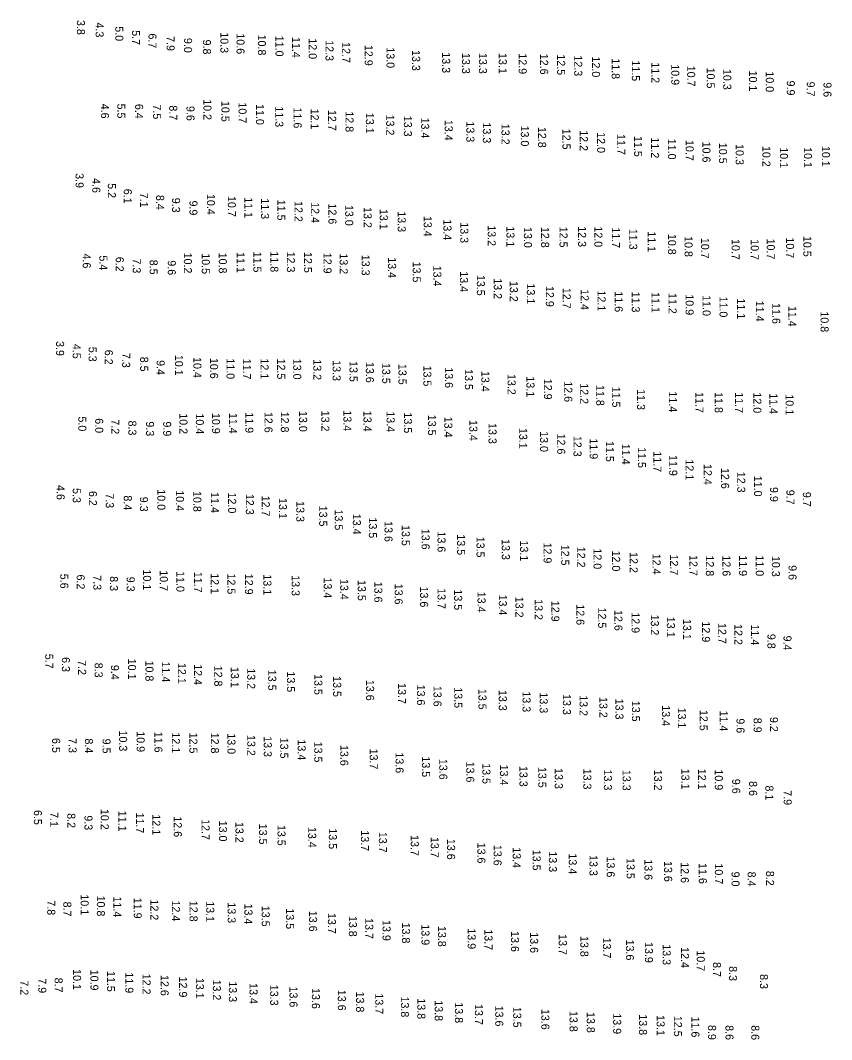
# Model space of a CAD drawing. Extents: x 988130 to 1132882, y 654656 to 841453.
# Drawn here: x 1112035 to 1112542, y 658070 to 658706 of the extents above; entities that cross this region are included whole.
import ezdxf

# ---------------------------------------------------------------- set-up
doc = ezdxf.new("R2010")
doc.units = 0
doc.layers.add('V-TOPO-SOUN', color=7, linetype='Continuous')

msp = doc.modelspace()

# ---------------------------------------------------------------- texts
at = {"layer": 'V-TOPO-SOUN'}
for s, p in [('3.8', (1112070.72, 658706.48)), ('4.3', (1112082.4, 658704.91)), ('5.0', (1112094.72, 658702.53)), ('5.7', (1112105.12, 658700.11)), ('6.7', (1112115.4, 658698.07)), ('7.9', (1112126.73, 658696.4)), ('9.0', (1112137.63, 658695.27)), ('10.3 ', (1112160.31, 658698.8)), ('10.6 ', (1112170.38, 658698.14)), ('10.8 ', (1112183.74, 658697.36)), ('11.0 ', (1112194.7, 658696.66)), ('11.4 ', (1112205.07, 658695.88)), ('9.8', (1112149.4, 658694.23)), ('12.0 ', (1112215.47, 658695.04)), ('12.3 ', (1112225.94, 658693.86)), ('12.7 ', (1112236.35, 658692.64)), ('12.9 ', (1112250.38, 658690.9)), ('13.0 ', (1112264.01, 658689.42)), ('13.3 ', (1112280.01, 658687.68)), ('13.3 ', (1112298.74, 658686.31)), ('13.3 ', (1112311.15, 658685.88)), ('13.3 ', (1112321.71, 658685.88)), ('13.1 ', (1112334.11, 658685.84)), ('12.9 ', (1112346.54, 658685.65)), ('12.6 ', (1112359.92, 658685.38)), ('12.5 ', (1112370.54, 658685)), ('12.3 ', (1112381.22, 658684.35)), ('12.0 ', (1112392.28, 658683.68)), ('11.8 ', (1112404.59, 658682.55)), ('11.5 ', (1112417.19, 658681.25)), ('11.2 ', (1112429.41, 658680.02)), ('10.9 ', (1112441.78, 658678.81)), ('10.7 ', (1112451.74, 658677.91)), ('10.5 ', (1112463.94, 658676.73)), ('10.3 ', (1112474.25, 658675.87)), ('10.1 ', (1112490.34, 658674.87)), ('10.0 ', (1112500.78, 658674.37)), ('9.9', (1112513.94, 658668.62)), ('9.7', (1112526.38, 658667.98)), ('9.6', (1112536.81, 658667.57)), ('10.2 ', (1112149.73, 658656.98)), ('4.6', (1112085.75, 658654.18)), ('5.5', (1112095.95, 658654.26)), ('6.4', (1112107.07, 658654.05)), ('7.5', (1112118.26, 658653.72)), ('8.7', (1112128.35, 658653.14)), ('9.6', (1112139.15, 658652.75)), ('10.5 ', (1112160.96, 658655.89)), ('10.7 ', (1112171.65, 658654.99)), ('11.0 ', (1112182.53, 658653.93)), ('11.3 ', (1112194.57, 658652.56)), ('11.6 ', (1112206, 658651.8)), ('12.1 ', (1112216.73, 658651.12)), ('12.7 ', (1112227.58, 658650.29)), ('12.8 ', (1112238.42, 658649.41)), ('13.1 ', (1112251.15, 658648.49)), ('13.2 ', (1112263.83, 658647.36)), ('13.3 ', (1112274.86, 658646.63)), ('13.4 ', (1112285.65, 658645.53)), ('13.4 ', (1112300.34, 658644.11)), ('13.3 ', (1112313.88, 658643.13)), ('13.3 ', (1112324.17, 658642.46)), ('13.2 ', (1112335.81, 658641.64)), ('13.0 ', (1112347.88, 658640.53)), ('12.8 ', (1112358.67, 658639.68)), ('12.5 ', (1112373.88, 658638.55)), ('12.2 ', (1112384.7, 658637.6)), ('12.0 ', (1112395.49, 658636.38)), ('11.7 ', (1112408.02, 658635.25)), ('11.5 ', (1112418.6, 658634.02)), ('11.2 ', (1112429.18, 658633.08)), ('11.0 ', (1112439.72, 658632.28)), ('10.7 ', (1112450.78, 658631.49)), ('10.6 ', (1112461.25, 658630.48)), ('10.5 ', (1112471.61, 658629.75)), ('10.3 ', (1112482.01, 658628.96)), ('10.2 ', (1112498.67, 658627.8)), ('10.1 ', (1112509.63, 658626.96)), ('10.1 ', (1112524.61, 658627.05)), ('10.1 ', (1112535.82, 658627.81)), ('3.9', (1112069.9, 658610.79)), ('4.6', (1112080.33, 658607.7)), ('5.2', (1112090.03, 658604.5)), ('6.1', (1112099.98, 658601.01)), ('7.1', (1112110.15, 658598.58)), ('8.4', (1112120.19, 658597.17)), ('9.3', (1112130.13, 658595.4)), ('9.9', (1112140.98, 658593.69)), ('10.4 ', (1112151.9, 658597.78)), ('10.7 ', (1112164.96, 658596.51)), ('11.1 ', (1112175.34, 658595.76)), ('11.3 ', (1112185.66, 658595.09)), ('11.5 ', (1112195.85, 658594.22)), ('12.2 ', (1112206.6, 658593.38)), ('12.4 ', (1112217, 658592.66)), ('12.6 ', (1112227.76, 658591.85)), ('13.0 ', (1112238.23, 658590.95)), ('13.2 ', (1112249.77, 658589.63)), ('13.1 ', (1112259.78, 658588.47)), ('13.3 ', (1112271, 658586.99)), ('13.4 ', (1112287.24, 658584.09)), ('13.4 ', (1112299.57, 658581.92)), ('13.3 ', (1112310.09, 658580.13)), ('13.2 ', (1112327.17, 658578.25)), ('13.1 ', (1112338.88, 658577.56)), ('13.0 ', (1112349.79, 658577.14)), ('12.8 ', (1112360.54, 658577.2)), ('12.5 ', (1112372.03, 658577.35)), ('12.3 ', (1112383.64, 658577.63)), ('12.0 ', (1112393.77, 658577.54)), ('11.7 ', (1112404.7, 658576.99)), ('11.3 ', (1112415.57, 658576.02)), ('11.1 ', (1112427.08, 658574.49)), ('10.8 ', (1112439.8, 658572.86)), ('10.8 ', (1112450.1, 658571.47)), ('10.7 ', (1112460.44, 658570.37)), ('10.7 ', (1112479.5, 658569.62)), ('10.7 ', (1112491.42, 658569.54)), ('10.7 ', (1112501.43, 658569.94)), ('10.7 ', (1112513.46, 658570.63)), ('10.5 ', (1112524.25, 658571.58)), ('11.1 ', (1112170.46, 658561.48)), ('11.5 ', (1112180.89, 658561.78)), ('11.8 ', (1112191.52, 658561.92)), ('12.3 ', (1112201.82, 658561.8)), ('12.5 ', (1112212.51, 658561.55)), ('4.6', (1112074.36, 658560.58)), ('5.4', (1112084.75, 658559.42)), ('6.2', (1112094.97, 658558.54)), ('7.3', (1112105.58, 658557.51)), ('8.5', (1112116.16, 658556.71)), ('9.6', (1112127.46, 658556.33)), ('10.2 ', (1112137.5, 658561.15)), ('10.5 ', (1112148.69, 658560.76)), ('10.8 ', (1112159.31, 658561.13)), ('12.9 ', (1112224.7, 658561.08)), ('13.2 ', (1112234.78, 658560.69)), ('13.3 ', (1112248.51, 658559.82)), ('13.4 ', (1112264.99, 658558.28)), ('13.5 ', (1112280.38, 658555.55)), ('13.4 ', (1112293.21, 658553.03)), ('13.4 ', (1112309.87, 658549.49)), ('13.5 ', (1112320.42, 658547.24)), ('13.2 ', (1112331.01, 658545.14)), ('13.2 ', (1112341, 658543.47)), ('13.1 ', (1112351.63, 658541.88)), ('12.9 ', (1112363.48, 658540.29)), ('12.7 ', (1112374.03, 658539.16)), ('12.4 ', (1112385.25, 658538.31)), ('12.1 ', (1112395.79, 658537.5)), ('11.6 ', (1112406.47, 658536.97)), ('11.3 ', (1112417.12, 658536.81)), ('11.1 ', (1112429.52, 658536.47)), ('11.2 ', (1112440.13, 658535.92)), ('10.9 ', (1112450.75, 658535.09)), ('11.0 ', (1112461.35, 658534.56)), ('11.0 ', (1112471.9, 658533.72)), ('11.1 ', (1112482.91, 658532.56)), ('11.4 ', (1112494.6, 658531.07)), ('11.6 ', (1112504.85, 658529.6)), ('11.4 ', (1112514.92, 658527.87)), ('10.8 ', (1112535.02, 658524.44)), ('3.9', (1112057.73, 658505.88)), ('4.5', (1112068.1, 658504.15)), ('5.3', (1112078.07, 658502.32)), ('6.2', (1112088.14, 658500.46)), ('7.3', (1112099, 658498.5)), ('8.5', (1112110.22, 658496.11)), ('9.4', (1112120.52, 658493.99)), ('10.1 ', (1112131.97, 658497.29)), ('10.4 ', (1112143.44, 658495.9)), ('10.6 ', (1112153.87, 658495.39)), ('11.0 ', (1112164.13, 658495.12)), ('11.7 ', (1112174.37, 658494.93)), ('12.1 ', (1112185.38, 658495.06)), ('12.5 ', (1112195.74, 658494.97)), ('13.0 ', (1112205.78, 658494.85)), ('13.2 ', (1112218.31, 658494.51)), ('13.3 ', (1112230.38, 658493.96)), ('13.5 ', (1112240.92, 658493.41)), ('13.6 ', (1112251.11, 658492.86)), ('13.5 ', (1112261.32, 658492.24)), ('13.5 ', (1112271.49, 658491.66)), ('13.5 ', (1112287.02, 658490.61)), ('13.6 ', (1112300.49, 658489.53)), ('13.5 ', (1112312.95, 658488.37)), ('13.4 ', (1112323.22, 658487.25)), ('13.2 ', (1112339.62, 658485.35)), ('13.1 ', (1112351.39, 658483.86)), ('12.9 ', (1112362.3, 658482.36)), ('12.6 ', (1112374.98, 658480.78)), ('12.2 ', (1112384.98, 658479.57)), ('11.8 ', (1112394.95, 658478.45)), ('11.5 ', (1112404.93, 658477.44)), ('11.3 ', (1112420.42, 658475.86)), ('11.4 ', (1112440.33, 658474.45)), ('11.7 ', (1112456.87, 658474.06)), ('11.8 ', (1112468.96, 658473.99)), ('11.7 ', (1112481.66, 658473.94)), ('12.0 ', (1112493.04, 658473.82)), ('11.4 ', (1112503.11, 658473.32)), ('10.1 ', (1112513.17, 658472.61)), ('10.2 ', (1112134.75, 658460.8)), ('10.4 ', (1112144.97, 658460.7)), ('10.9 ', (1112155.04, 658460.97)), ('11.4 ', (1112165.75, 658461.04)), ('11.9 ', (1112175.87, 658461.42)), ('12.6 ', (1112187.85, 658461.66)), ('12.8 ', (1112198.04, 658461.8)), ('13.0 ', (1112209.46, 658462.24)), ('13.2 ', (1112223.3, 658462.42)), ('13.4 ', (1112237.11, 658462.62)), ('13.4 ', (1112249.64, 658462.34)), ('13.4 ', (1112264.08, 658462.03)), ('13.5 ', (1112274.91, 658461.29)), ('13.5 ', (1112289.96, 658459.88)), ('5.0', (1112071.61, 658458.81)), ('6.0', (1112082.14, 658457.68)), ('7.2', (1112092.21, 658457)), ('8.3', (1112102.87, 658456.24)), ('9.3', (1112113.9, 658455.73)), ('9.9', (1112124.59, 658455.69)), ('13.4 ', (1112300.11, 658458.65)), ('13.4 ', (1112315.74, 658456.58)), ('13.3 ', (1112327.71, 658454.67)), ('13.1 ', (1112346.83, 658451.64)), ('13.0 ', (1112359.88, 658449.62)), ('12.6 ', (1112370.6, 658448.12)), ('12.3 ', (1112380.77, 658446.69)), ('11.9 ', (1112390.88, 658445.1)), ('11.5 ', (1112400.96, 658443.43)), ('11.4 ', (1112410.98, 658441.74)), ('11.5 ', (1112420.96, 658439.63)), ('11.7 ', (1112430.67, 658437.03)), ('11.9 ', (1112440.53, 658434.69)), ('12.1 ', (1112450.74, 658431.99)), ('12.4 ', (1112462.08, 658429.1)), ('12.6 ', (1112472.93, 658426.63)), ('12.3 ', (1112482.97, 658424.24)), ('11.0 ', (1112493.44, 658421.75)), ('4.6', (1112058.09, 658415.96)), ('5.3', (1112068.13, 658414.07)), ('6.2', (1112078.23, 658412.27)), ('7.3', (1112088.76, 658410.8)), ('8.4', (1112100.01, 658409.51)), ('9.3', (1112110.08, 658408.65)), ('10.0 ', (1112120.91, 658413.28)), ('10.4 ', (1112132.53, 658412.67)), ('10.8 ', (1112143.37, 658412.22)), ('11.4 ', (1112154.39, 658411.54)), ('12.0 ', (1112165.12, 658411.28)), ('12.3 ', (1112176.2, 658410.43)), ('12.7 ', (1112186.16, 658409.36)), ('9.9', (1112503.47, 658414.72)), ('9.7', (1112513.7, 658413)), ('9.7', (1112523.96, 658411.69)), ('13.1 ', (1112196.82, 658407.85)), ('13.3 ', (1112207.7, 658405.92)), ('13.5 ', (1112221.97, 658403.06)), ('13.5 ', (1112231.73, 658400.69)), ('13.4 ', (1112243, 658397.99)), ('13.5 ', (1112253.01, 658395.72)), ('13.6 ', (1112262.77, 658393.42)), ('13.5 ', (1112273.53, 658390.99)), ('13.6 ', (1112285.93, 658388.64)), ('13.6 ', (1112295.86, 658386.95)), ('13.5 ', (1112308.09, 658385.17)), ('13.5 ', (1112320.2, 658383.69)), ('13.3 ', (1112336, 658382.19)), ('13.1 ', (1112347.44, 658381.32)), ('12.9 ', (1112362.08, 658380.03)), ('12.5 ', (1112373.09, 658378.69)), ('12.2 ', (1112383.07, 658377.44)), ('12.0 ', (1112393.25, 658376.37)), ('12.0 ', (1112404.88, 658375.03)), ('12.2 ', (1112415.85, 658374.05)), ('12.4 ', (1112430.11, 658373.08)), ('12.7 ', (1112441.04, 658372.57)), ('12.7 ', (1112453.16, 658372.24)), ('12.8 ', (1112463.39, 658371.99)), ('12.6 ', (1112473.77, 658371.99)), ('11.9 ', (1112484.08, 658372.09)), ('11.0 ', (1112494.52, 658372.01)), ('10.3 ', (1112504.61, 658371.67)), ('9.6', (1112515.03, 658365.91)), ('5.6', (1112060.35, 658360.55)), ('6.2', (1112070.6, 658360.05)), ('7.3', (1112080.97, 658359.62)), ('8.3', (1112091.32, 658359)), ('9.3', (1112101.79, 658358.67)), ('10.1 ', (1112112.04, 658363.23)), ('10.7 ', (1112122.48, 658362.72)), ('11.0 ', (1112132.8, 658362.16)), ('11.7 ', (1112143.89, 658361.75)), ('12.1 ', (1112154.29, 658360.88)), ('12.5 ', (1112164.69, 658360.7)), ('12.9 ', (1112175.65, 658360.53)), ('13.1 ', (1112187.15, 658360.18)), ('13.3 ', (1112204.78, 658359.66)), ('13.4 ', (1112224.84, 658358.19)), ('13.4 ', (1112235.1, 658357.29)), ('13.5 ', (1112246.09, 658356.66)), ('13.6 ', (1112256.4, 658355.59)), ('13.6 ', (1112269.13, 658354.34)), ('13.6 ', (1112284.98, 658352.57)), ('13.7 ', (1112295.88, 658351.54)), ('13.5 ', (1112306.24, 658350.76)), ('13.4 ', (1112320.84, 658349.35)), ('13.4 ', (1112334.16, 658347.55)), ('13.2 ', (1112344.49, 658346.18)), ('13.2 ', (1112356.49, 658344.67)), ('12.9 ', (1112366.93, 658343.64)), ('12.6 ', (1112382.54, 658341.47)), ('12.5 ', (1112396.15, 658339.44)), ('12.6 ', (1112406.3, 658337.89)), ('12.9 ', (1112417, 658336.48)), ('13.2 ', (1112429.04, 658335.06)), ('13.1 ', (1112439.06, 658333.67)), ('13.1 ', (1112449.2, 658332.31)), ('12.9 ', (1112461.01, 658330.74)), ('12.7 ', (1112471.13, 658329.77)), ('12.2 ', (1112481.2, 658329.08)), ('11.4 ', (1112491.61, 658328.83)), ('9.8', (1112501.85, 658322.99)), ('9.4', (1112511.85, 658321.92)), ('5.7', (1112050.96, 658310.56)), ('6.3', (1112061.35, 658308.47)), ('7.2', (1112071.49, 658306.55)), ('10.1 ', (1112102.65, 658307.5)), ('8.3', (1112081.82, 658304.98)), ('9.4', (1112091.98, 658303.6)), ('10.8 ', (1112113.53, 658306.32)), ('11.4 ', (1112123.75, 658305.71)), ('12.1 ', (1112133.8, 658304.82)), ('12.4 ', (1112143.82, 658304.03)), ('12.8 ', (1112156.47, 658303.13)), ('13.1 ', (1112166.81, 658302.33)), ('13.2 ', (1112177.04, 658301.53)), ('13.5 ', (1112190.17, 658300.55)), ('13.5 ', (1112201.87, 658299.52)), ('13.5 ', (1112218.94, 658297.88)), ('13.5 ', (1112230.7, 658296.58)), ('13.6 ', (1112251.29, 658294.26)), ('13.7 ', (1112271.17, 658292.23)), ('13.6 ', (1112283.01, 658291.28)), ('13.6 ', (1112293.35, 658290.53)), ('13.5 ', (1112306.32, 658289.62)), ('13.5 ', (1112321.43, 658288.66)), ('13.3 ', (1112334.1, 658287.98)), ('13.3 ', (1112348.95, 658287.06)), ('13.3 ', (1112359.66, 658286.41)), ('13.3 ', (1112374.12, 658285.38)), ('13.2 ', (1112384.54, 658284.67)), ('13.2 ', (1112396.92, 658283.56)), ('13.3 ', (1112406.94, 658282.5)), ('13.5 ', (1112417.24, 658281.18)), ('13.4 ', (1112436.01, 658278.37)), ('13.1 ', (1112445.95, 658276.93)), ('12.5 ', (1112459.5, 658275.48)), ('11.4 ', (1112472.09, 658275.08)), ('9.6', (1112482.52, 658270.2)), ('8.9', (1112493.21, 658270.57)), ('9.2', (1112503.43, 658271.07)), ('10.3 ', (1112097.1, 658262.62)), ('10.9 ', (1112108.03, 658262.14)), ('6.5', (1112055.25, 658257.95)), ('7.3', (1112065.56, 658257.9)), ('8.4', (1112075.75, 658257.65)), ('9.5', (1112086.75, 658257.54)), ('11.6 ', (1112119.12, 658261.86)), ('12.1 ', (1112130.05, 658261.46)), ('12.5 ', (1112140.95, 658261.3)), ('12.8 ', (1112154.38, 658261.28)), ('13.0 ', (1112164.71, 658260.85)), ('13.2 ', (1112177.09, 658259.8)), ('13.3 ', (1112187.38, 658259.08)), ('13.5 ', (1112197.66, 658258.15)), ('13.4 ', (1112208.58, 658257.03)), ('13.5 ', (1112218.91, 658255.67)), ('13.6 ', (1112235.16, 658253.6)), ('13.7 ', (1112253.55, 658251.34)), ('13.6 ', (1112269.68, 658248.96)), ('13.5 ', (1112286.19, 658246.45)), ('13.6 ', (1112296.94, 658244.91)), ('13.6 ', (1112313.81, 658243.21)), ('13.5 ', (1112323.88, 658242.21)), ('13.4 ', (1112334.9, 658241.32)), ('13.3 ', (1112347.03, 658240.5)), ('13.5 ', (1112358.77, 658239.89)), ('13.3 ', (1112369.08, 658239.12)), ('13.3 ', (1112386.87, 658238.8)), ('13.3 ', (1112399.74, 658238.24)), ('13.3 ', (1112411.42, 658238.04)), ('13.2 ', (1112431.05, 658238.13)), ('13.1 ', (1112448.11, 658238.77)), ('12.1 ', (1112458.51, 658238.73)), ('10.9 ', (1112468.98, 658238.32)), ('9.6', (1112479.83, 658232.44)), ('8.6', (1112490.39, 658231.01)), ('8.1', (1112500.57, 658228.3)), ('7.9', (1112511.97, 658225.3)), ('6.5', (1112043.85, 658212.95)), ('7.1', (1112054.04, 658211.59)), ('8.2', (1112064.75, 658210.98)), ('10.2 ', (1112085.59, 658213.64)), ('11.1 ', (1112096.65, 658212.48)), ('11.7 ', (1112107.59, 658211.37)), ('9.3', (1112075.44, 658209.61)), ('12.1 ', (1112117.8, 658210.25)), ('12.6 ', (1112131.2, 658208.99)), ('12.7 ', (1112148.56, 658207.24)), ('13.0 ', (1112159.44, 658206.31)), ('13.2 ', (1112169.72, 658205.5)), ('13.5 ', (1112184.45, 658204.43)), ('13.5 ', (1112195.97, 658203.65)), ('13.4 ', (1112215.1, 658202.39)), ('13.5 ', (1112228.01, 658201.53)), ('13.7 ', (1112248.08, 658200.26)), ('13.7 ', (1112259.24, 658199.31)), ('13.7 ', (1112279.16, 658197.27)), ('13.7 ', (1112291.61, 658196.15)), ('13.6 ', (1112301.84, 658194.93)), ('13.6 ', (1112320.76, 658192.56)), ('13.6 ', (1112330.89, 658191.18)), ('13.4 ', (1112342.82, 658189.7)), ('13.5 ', (1112355.27, 658188.15)), ('13.3 ', (1112365.37, 658187.14)), ('13.4 ', (1112377.79, 658185.84)), ('13.3 ', (1112390.75, 658184.82)), ('13.6 ', (1112401.49, 658183.9)), ('13.5 ', (1112413.91, 658182.95)), ('13.6 ', (1112425.03, 658182.14)), ('13.6 ', (1112437.34, 658181.08)), ('12.6 ', (1112447.74, 658180.34)), ('11.6 ', (1112458.98, 658179.82)), ('10.7 ', (1112469.01, 658179.58)), ('9.0', (1112479.41, 658174.48)), ('8.4', (1112489.53, 658174.46)), ('8.2', (1112500.98, 658174.94)), ('7.8', (1112052.2, 658156.54)), ('8.7', (1112062.26, 658155.72)), ('10.1 ', (1112073.07, 658160.25)), ('10.8 ', (1112083.18, 658159.51)), ('11.4 ', (1112093.5, 658158.93)), ('11.9 ', (1112106.19, 658158.12)), ('12.2 ', (1112116.62, 658157.06)), ('12.4 ', (1112130.05, 658156.43)), ('12.8 ', (1112141.08, 658156.23)), ('13.1 ', (1112151.47, 658155.96)), ('13.3 ', (1112164.85, 658155.28)), ('13.4 ', (1112175.31, 658154.52)), ('13.5 ', (1112186.12, 658153.11)), ('13.5 ', (1112201.29, 658151.54)), ('13.6 ', (1112215.67, 658150.01)), ('13.7 ', (1112227.42, 658148.64)), ('13.8 ', (1112240.53, 658146.82)), ('13.7 ', (1112250.74, 658145.42)), ('13.9 ', (1112261.55, 658144.21)), ('13.8 ', (1112273.66, 658142.64)), ('13.9 ', (1112285.84, 658141.51)), ('13.8 ', (1112296.18, 658140.53)), ('13.9 ', (1112314.67, 658139.05)), ('13.7 ', (1112325.18, 658138.44)), ('13.6 ', (1112341.75, 658137.31)), ('13.6 ', (1112353.69, 658136.61)), ('13.7 ', (1112371.58, 658135.43)), ('13.8 ', (1112385.06, 658134.26)), ('13.7 ', (1112399.13, 658133.27)), ('13.6 ', (1112413.51, 658132)), ('13.9 ', (1112425.34, 658130.47)), ('13.3 ', (1112436.43, 658129.11)), ('12.4 ', (1112447.84, 658127.32)), ('10.7 ', (1112457.7, 658125.27)), ('8.7', (1112467.84, 658117.94)), ('10.1 ', (1112068.32, 658113.55)), ('10.9 ', (1112079.15, 658113.22)), ('11.5 ', (1112089.52, 658112.42)), ('11.9 ', (1112100.94, 658111.51)), ('12.2 ', (1112111.72, 658110.7)), ('12.6 ', (1112123, 658109.88)), ('8.3', (1112477.86, 658115.42)), ('8.3', (1112497.15, 658110.44)), ('7.2', (1112035.44, 658106.54)), ('7.9', (1112046.63, 658107.82)), ('8.7', (1112056.8, 658108.23)), ('12.9 ', (1112134.54, 658108.9)), ('13.1 ', (1112145.04, 658108.09)), ('13.2 ', (1112155.59, 658107.04)), ('13.3 ', (1112165.59, 658105.96)), ('13.4 ', (1112178.5, 658104.8)), ('13.3 ', (1112191.4, 658103.77)), ('13.6 ', (1112203.44, 658102.71)), ('13.6 ', (1112217.43, 658101.74)), ('13.6 ', (1112233.62, 658100.63)), ('13.8 ', (1112245.04, 658099.55)), ('13.7 ', (1112256.99, 658098.4)), ('13.8 ', (1112273.02, 658096.45)), ('13.8 ', (1112283.28, 658095.32)), ('13.8 ', (1112294.13, 658094.09)), ('13.8 ', (1112306.72, 658092.82)), ('13.7 ', (1112319.19, 658091.73)), ('13.6 ', (1112331.9, 658090.77)), ('13.5 ', (1112343.13, 658090.01)), ('13.6 ', (1112360.68, 658088.71)), ('13.8 ', (1112378.29, 658087.44)), ('13.8 ', (1112389.06, 658086.79)), ('13.9 ', (1112405.52, 658085.96)), ('13.8 ', (1112421.68, 658085.35)), ('13.1 ', (1112432.67, 658084.83)), ('12.5 ', (1112443.45, 658084.37)), ('11.6 ', (1112454.36, 658083.93)), ('8.9', (1112464.77, 658078.65)), ('8.6', (1112475.62, 658078.54)), ('8.6', (1112491.76, 658078.52))]:
    msp.add_text(s, height=5, rotation=270, dxfattribs=at).set_placement(p)

doc.saveas('drawing.dxf')
